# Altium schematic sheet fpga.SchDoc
size A
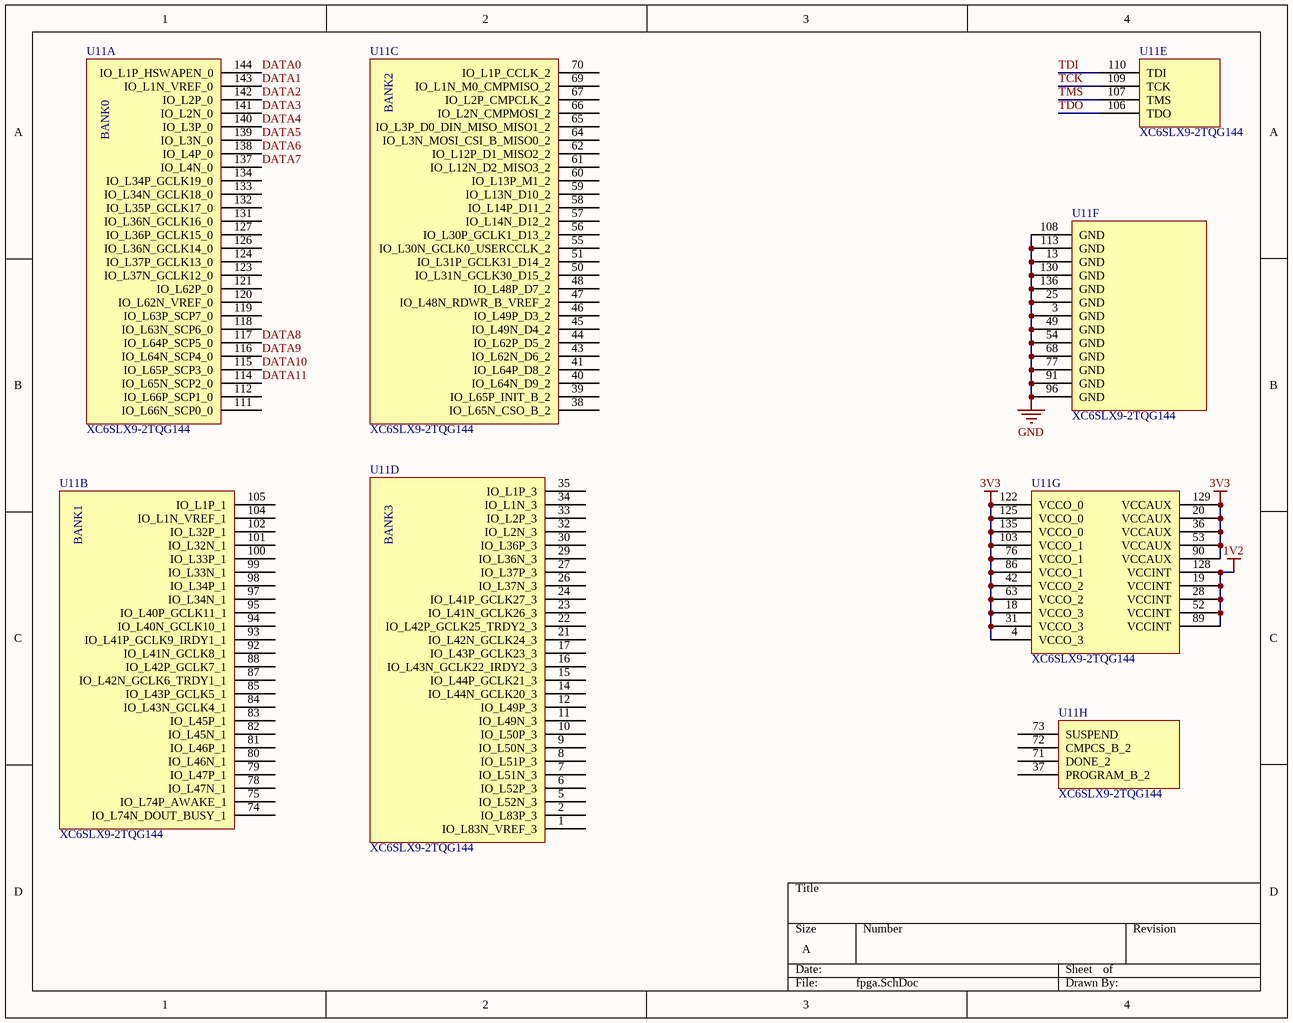
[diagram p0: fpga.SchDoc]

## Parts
U11  XC6SLX9-2TQG144  [TSQFP50P2200X2200X160-144N]  (parts A,B,C,D,E,F,G,H of 8)

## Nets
1V2: U11.19(VCCINT) U11.28(VCCINT) U11.52(VCCINT) U11.89(VCCINT) U11.128(VCCINT)
3V3: U11.4(VCCO_3) U11.18(VCCO_3) U11.20(VCCAUX) U11.31(VCCO_3) U11.36(VCCAUX) U11.42(VCCO_2) U11.53(VCCAUX) U11.63(VCCO_2) U11.76(VCCO_1) U11.86(VCCO_1) U11.90(VCCAUX) U11.103(VCCO_1) U11.122(VCCO_0) U11.125(VCCO_0) U11.129(VCCAUX) U11.135(VCCO_0)
GND: U11.3(GND) U11.13(GND) U11.25(GND) U11.49(GND) U11.54(GND) U11.68(GND) U11.77(GND) U11.91(GND) U11.96(GND) U11.108(GND) U11.113(GND) U11.130(GND) U11.136(GND)
DATA0: U11.144(IO_L1P_HSWAPEN_0)
DATA1: U11.143(IO_L1N_VREF_0)
DATA2: U11.142(IO_L2P_0)
DATA3: U11.141(IO_L2N_0)
DATA4: U11.140(IO_L3P_0)
DATA5: U11.139(IO_L3N_0)
DATA6: U11.138(IO_L4P_0)
DATA7: U11.137(IO_L4N_0)
DATA8: U11.117(IO_L64P_SCP5_0)
DATA9: U11.116(IO_L64N_SCP4_0)
DATA10: U11.115(IO_L65P_SCP3_0)
DATA11: U11.114(IO_L65N_SCP2_0)
TCK: U11.109(TCK)
TDI: U11.110(TDI)
TDO: U11.106(TDO)
TMS: U11.107(TMS)

Not connected (* = marked no-connect by the designer): U11 1(IO_L83N_VREF_3) 2(IO_L83P_3) 5(IO_L52N_3) 6(IO_L52P_3) 7(IO_L51N_3) 8(IO_L51P_3) 9(IO_L50N_3) 10(IO_L50P_3) 11(IO_L49N_3) 12(IO_L49P_3) 14(IO_L44N_GCLK20_3) 15(IO_L44P_GCLK21_3) 16(IO_L43N_GCLK22_IRDY2_3) 17(IO_L43P_GCLK23_3) 21(IO_L42N_GCLK24_3) 22(IO_L42P_GCLK25_TRDY2_3) 23(IO_L41N_GCLK26_3) 24(IO_L41P_GCLK27_3) 26(IO_L37N_3) 27(IO_L37P_3) 29(IO_L36N_3) 30(IO_L36P_3) 32(IO_L2N_3) 33(IO_L2P_3) 34(IO_L1N_3) 35(IO_L1P_3) 37(PROGRAM_B_2) 38(IO_L65N_CSO_B_2) 39(IO_L65P_INIT_B_2) 40(IO_L64N_D9_2) 41(IO_L64P_D8_2) 43(IO_L62N_D6_2) 44(IO_L62P_D5_2) 45(IO_L49N_D4_2) 46(IO_L49P_D3_2) 47(IO_L48N_RDWR_B_VREF_2) 48(IO_L48P_D7_2) 50(IO_L31N_GCLK30_D15_2) 51(IO_L31P_GCLK31_D14_2) 55(IO_L30N_GCLK0_USERCCLK_2) 56(IO_L30P_GCLK1_D13_2) 57(IO_L14N_D12_2) 58(IO_L14P_D11_2) 59(IO_L13N_D10_2) 60(IO_L13P_M1_2) 61(IO_L12N_D2_MISO3_2) 62(IO_L12P_D1_MISO2_2) 64(IO_L3N_MOSI_CSI_B_MISO0_2) 65(IO_L3P_D0_DIN_MISO_MISO1_2) 66(IO_L2N_CMPMOSI_2) 67(IO_L2P_CMPCLK_2) 69(IO_L1N_M0_CMPMISO_2) 70(IO_L1P_CCLK_2) 71(DONE_2) 72(CMPCS_B_2) 73(SUSPEND) 74(IO_L74N_DOUT_BUSY_1) 75(IO_L74P_AWAKE_1) 78(IO_L47N_1) 79(IO_L47P_1) 80(IO_L46N_1) 81(IO_L46P_1) 82(IO_L45N_1) 83(IO_L45P_1) 84(IO_L43N_GCLK4_1) 85(IO_L43P_GCLK5_1) 87(IO_L42N_GCLK6_TRDY1_1) 88(IO_L42P_GCLK7_1) 92(IO_L41N_GCLK8_1) 93(IO_L41P_GCLK9_IRDY1_1) 94(IO_L40N_GCLK10_1) 95(IO_L40P_GCLK11_1) 97(IO_L34N_1) 98(IO_L34P_1) 99(IO_L33N_1) 100(IO_L33P_1) 101(IO_L32N_1) 102(IO_L32P_1) 104(IO_L1N_VREF_1) 105(IO_L1P_1) 111(IO_L66N_SCP0_0) 112(IO_L66P_SCP1_0) 118(IO_L63N_SCP6_0) 119(IO_L63P_SCP7_0) 120(IO_L62N_VREF_0) 121(IO_L62P_0) 123(IO_L37N_GCLK12_0) 124(IO_L37P_GCLK13_0) 126(IO_L36N_GCLK14_0) 127(IO_L36P_GCLK15_0) 131(IO_L36N_GCLK16_0) 132(IO_L35P_GCLK17_0) 133(IO_L34N_GCLK18_0) 134(IO_L34P_GCLK19_0)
